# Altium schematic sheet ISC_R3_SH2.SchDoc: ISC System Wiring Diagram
size C; DrawnBy: Filiberto Clara; Engineer: Filiberto Clara; Organization: LIGO Laboratory; Address1: California Institute of Technology; Address2: Massachusetts Institute of Technology; SheetNumber: 18; SheetTotal: 39
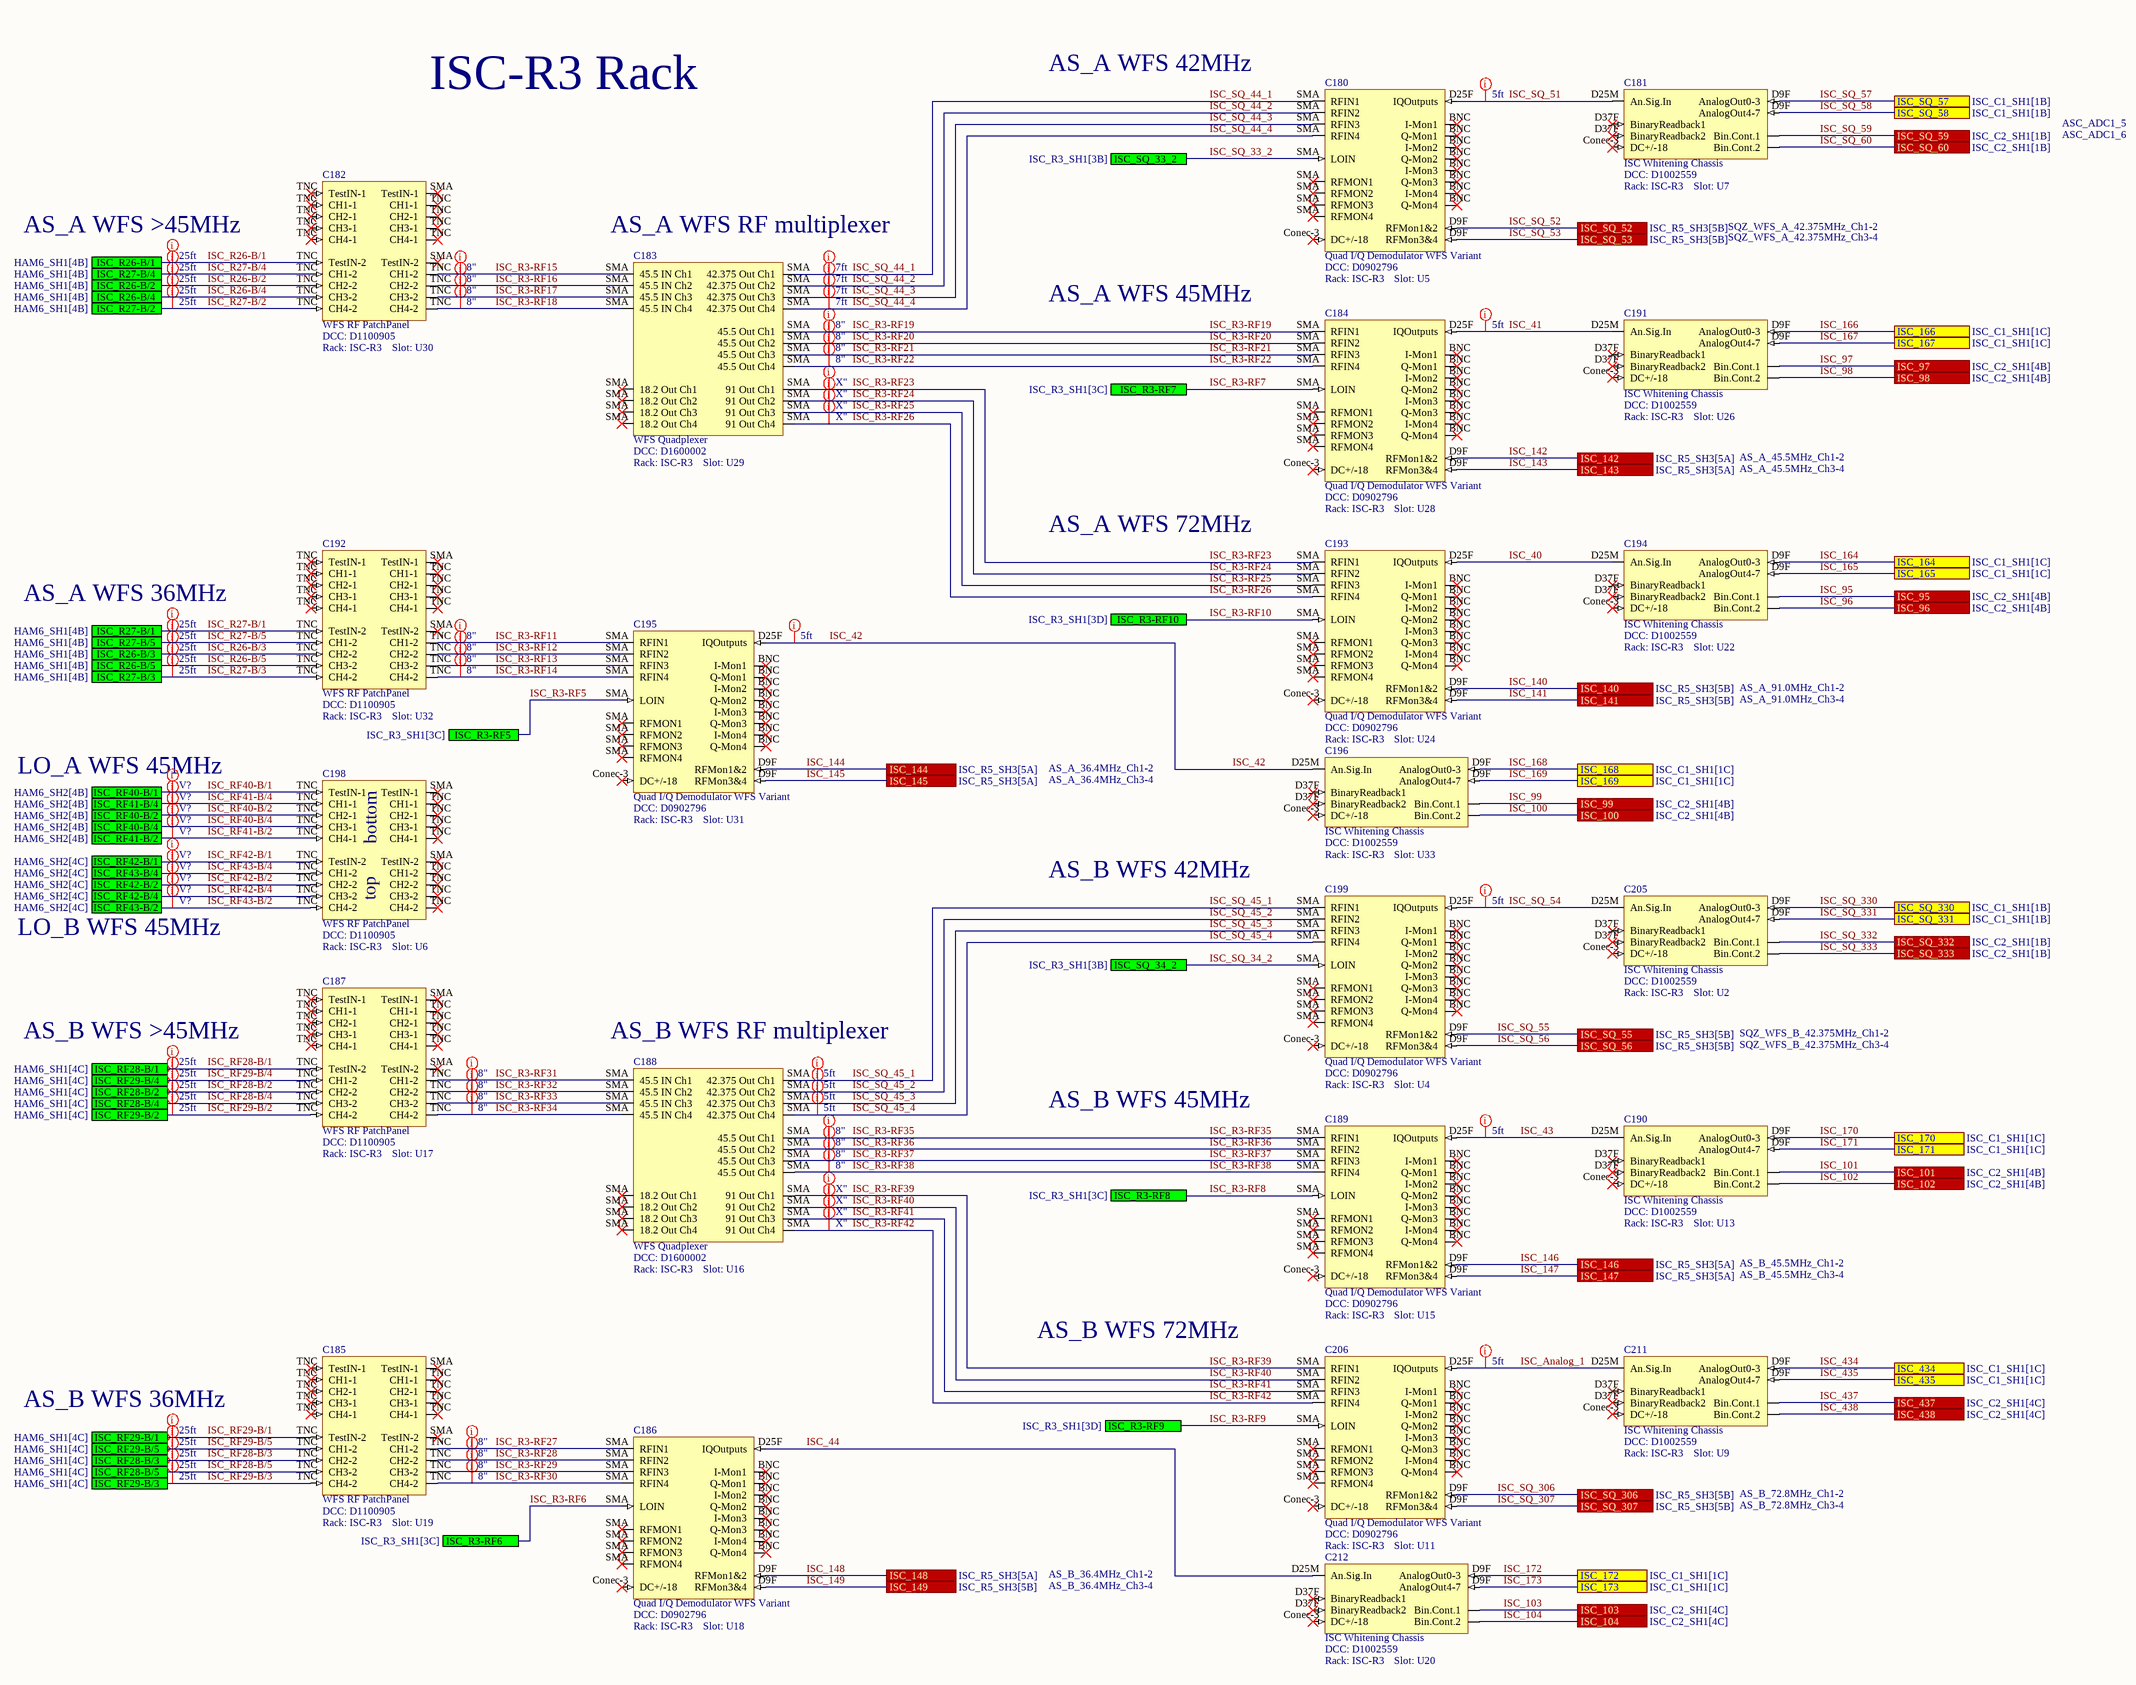
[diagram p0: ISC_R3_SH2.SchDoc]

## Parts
C180  Quad I/Q Demodulator WFS Variant  DCC: D0902796  Rack: ISC-R3  Slot: U5
C181  ISC Whitening Chassis  DCC: D1002559  Rack: ISC-R3  Slot: U7
C182  WFS RF PatchPanel  DCC: D1100905  Rack: ISC-R3  Slot: U30
C183  WFS Quadplexer  DCC: D1600002  Rack: ISC-R3  Slot: U29
C184  Quad I/Q Demodulator WFS Variant  DCC: D0902796  Rack: ISC-R3  Slot: U28
C185  WFS RF PatchPanel  DCC: D1100905  Rack: ISC-R3  Slot: U19
C186  Quad I/Q Demodulator WFS Variant  DCC: D0902796  Rack: ISC-R3  Slot: U18
C187  WFS RF PatchPanel  DCC: D1100905  Rack: ISC-R3  Slot: U17
C188  WFS Quadplexer  DCC: D1600002  Rack: ISC-R3  Slot: U16
C189  Quad I/Q Demodulator WFS Variant  DCC: D0902796  Rack: ISC-R3  Slot: U15
C190  ISC Whitening Chassis  DCC: D1002559  Rack: ISC-R3  Slot: U13
C191  ISC Whitening Chassis  DCC: D1002559  Rack: ISC-R3  Slot: U26
C192  WFS RF PatchPanel  DCC: D1100905  Rack: ISC-R3  Slot: U32
C193  Quad I/Q Demodulator WFS Variant  DCC: D0902796  Rack: ISC-R3  Slot: U24
C194  ISC Whitening Chassis  DCC: D1002559  Rack: ISC-R3  Slot: U22
C195  Quad I/Q Demodulator WFS Variant  DCC: D0902796  Rack: ISC-R3  Slot: U31
C196  ISC Whitening Chassis  DCC: D1002559  Rack: ISC-R3  Slot: U33
C198  WFS RF PatchPanel  DCC: D1100905  Rack: ISC-R3  Slot: U6
C199  Quad I/Q Demodulator WFS Variant  DCC: D0902796  Rack: ISC-R3  Slot: U4
C205  ISC Whitening Chassis  DCC: D1002559  Rack: ISC-R3  Slot: U2
C206  Quad I/Q Demodulator WFS Variant  DCC: D0902796  Rack: ISC-R3  Slot: U11
C211  ISC Whitening Chassis  DCC: D1002559  Rack: ISC-R3  Slot: U9
C212  ISC Whitening Chassis  DCC: D1002559  Rack: ISC-R3  Slot: U20

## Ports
ISC_95 (see ISC_C2_SH1[4B]), ISC_96 (see ISC_C2_SH1[4B]), ISC_97 (see ISC_C2_SH1[4B]), ISC_98 (see ISC_C2_SH1[4B]), ISC_99 (see ISC_C2_SH1[4B]), ISC_100 (see ISC_C2_SH1[4B]), ISC_101 (see ISC_C2_SH1[4B]), ISC_102 (see ISC_C2_SH1[4B]), ISC_103 (see ISC_C2_SH1[4C]), ISC_104 (see ISC_C2_SH1[4C]), ISC_140 (see ISC_R5_SH3[5B]), ISC_141 (see ISC_R5_SH3[5B]), ISC_142 (see ISC_R5_SH3[5A]), ISC_143 (see ISC_R5_SH3[5A]), ISC_144 (see ISC_R5_SH3[5A]), ISC_145 (see ISC_R5_SH3[5A]), ISC_146 (see ISC_R5_SH3[5A]), ISC_147 (see ISC_R5_SH3[5A]), ISC_148 (see ISC_R5_SH3[5A]), ISC_149 (see ISC_R5_SH3[5B]), ISC_164 (see ISC_C1_SH1[1C]), ISC_165 (see ISC_C1_SH1[1C]), ISC_166 (see ISC_C1_SH1[1C]), ISC_167 (see ISC_C1_SH1[1C]), ISC_168 (see ISC_C1_SH1[1C]), ISC_169 (see ISC_C1_SH1[1C]), ISC_170 (see ISC_C1_SH1[1C]), ISC_171 (see ISC_C1_SH1[1C]), ISC_172 (see ISC_C1_SH1[1C]), ISC_173 (see ISC_C1_SH1[1C]), ISC_434 (see ISC_C1_SH1[1C]), ISC_435 (see ISC_C1_SH1[1C]), ISC_437 (see ISC_C2_SH1[4C]), ISC_438 (see ISC_C2_SH1[4C]), ISC_R3-RF5 (see ISC_R3_SH1[3C]), ISC_R3-RF6 (see ISC_R3_SH1[3C]), ISC_R3-RF7 (see ISC_R3_SH1[3C]), ISC_R3-RF8 (see ISC_R3_SH1[3C]), ISC_R3-RF9 (see ISC_R3_SH1[3D]), ISC_R3-RF10 (see ISC_R3_SH1[3D]), ISC_R26-B/1 (see HAM6_SH1[4B]), ISC_R26-B/2 (see HAM6_SH1[4B]), ISC_R26-B/3 (see HAM6_SH1[4B]), ISC_R26-B/4 (see HAM6_SH1[4B]), ISC_R26-B/5 (see HAM6_SH1[4B]), ISC_R27-B/1 (see HAM6_SH1[4B]), ISC_R27-B/2 (see HAM6_SH1[4B]), ISC_R27-B/3 (see HAM6_SH1[4B]), ISC_R27-B/4 (see HAM6_SH1[4B]), ISC_R27-B/5 (see HAM6_SH1[4B]), ISC_RF28-B/1 (see HAM6_SH1[4C]), ISC_RF28-B/2 (see HAM6_SH1[4C]), ISC_RF28-B/3 (see HAM6_SH1[4C]), ISC_RF28-B/4 (see HAM6_SH1[4C]), ISC_RF28-B/5 (see HAM6_SH1[4C]), ISC_RF29-B/1 (see HAM6_SH1[4C]), ISC_RF29-B/2 (see HAM6_SH1[4C]), ISC_RF29-B/3 (see HAM6_SH1[4C]), ISC_RF29-B/4 (see HAM6_SH1[4C]), ISC_RF29-B/5 (see HAM6_SH1[4C]), ISC_RF40-B/1 (see HAM6_SH2[4B]), ISC_RF40-B/2 (see HAM6_SH2[4B]), ISC_RF40-B/4 (see HAM6_SH2[4B]), ISC_RF41-B/2 (see HAM6_SH2[4B]), ISC_RF41-B/4 (see HAM6_SH2[4B]), ISC_RF42-B/1 (see HAM6_SH2[4C]), ISC_RF42-B/2 (see HAM6_SH2[4C]), ISC_RF42-B/4 (see HAM6_SH2[4C]), ISC_RF43-B/2 (see HAM6_SH2[4C]), ISC_RF43-B/4 (see HAM6_SH2[4C]), ISC_SQ_33_2 (see ISC_R3_SH1[3B]), ISC_SQ_34_2 (see ISC_R3_SH1[3B]), ISC_SQ_52 (see ISC_R5_SH3[5B]), ISC_SQ_53 (see ISC_R5_SH3[5B]), ISC_SQ_55 (see ISC_R5_SH3[5B]), ISC_SQ_56 (see ISC_R5_SH3[5B]), ISC_SQ_57 (see ISC_C1_SH1[1B]), ISC_SQ_58 (see ISC_C1_SH1[1B]), ISC_SQ_59 (see ISC_C2_SH1[1B]), ISC_SQ_60 (see ISC_C2_SH1[1B]), ISC_SQ_306 (see ISC_R5_SH3[5B]), ISC_SQ_307 (see ISC_R5_SH3[5B]), ISC_SQ_330 (see ISC_C1_SH1[1B]), ISC_SQ_331 (see ISC_C1_SH1[1B]), ISC_SQ_332 (see ISC_C2_SH1[1B]), ISC_SQ_333 (see ISC_C2_SH1[1B])

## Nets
ISC_40: C193.D25F(IQOutputs) C194.D25M(An.Sig.In)
ISC_41: C184.D25F(IQOutputs) C191.D25M(An.Sig.In)
ISC_42: C195.D25F(IQOutputs) C196.D25M(An.Sig.In)
ISC_43: C189.D25F(IQOutputs) C190.D25M(An.Sig.In)
ISC_44: C186.D25F(IQOutputs) C212.D25M(An.Sig.In)
ISC_95: C194.D37F(BinaryReadback1) ; port ISC_95
ISC_96: C194.D37F(Bin.Cont.2) ; port ISC_96
ISC_97: C191.D37F(BinaryReadback1) ; port ISC_97
ISC_98: C191.D37F(Bin.Cont.2) ; port ISC_98
ISC_99: C196.D37F(BinaryReadback1) ; port ISC_99
ISC_100: C196.D37F(Bin.Cont.2) ; port ISC_100
ISC_101: C190.D37F(BinaryReadback1) ; port ISC_101
ISC_102: C190.D37F(Bin.Cont.2) ; port ISC_102
ISC_103: C212.D37F(BinaryReadback1) ; port ISC_103
ISC_104: C212.D37F(Bin.Cont.2) ; port ISC_104
ISC_140: C193.D9F(RFMon1&2) ; port ISC_140
ISC_141: C193.D9F(RFMon3&4) ; port ISC_141
ISC_142: C184.D9F(RFMon1&2) ; port ISC_142
ISC_143: C184.D9F(RFMon3&4) ; port ISC_143
ISC_144: C195.D9F(RFMon1&2) ; port ISC_144
ISC_145: C195.D9F(RFMon3&4) ; port ISC_145
ISC_146: C189.D9F(RFMon1&2) ; port ISC_146
ISC_147: C189.D9F(RFMon3&4) ; port ISC_147
ISC_148: C186.D9F(RFMon1&2) ; port ISC_148
ISC_149: C186.D9F(RFMon3&4) ; port ISC_149
ISC_164: C194.D9F(AnalogOut0-3) ; port ISC_164
ISC_165: C194.D9F(AnalogOut4-7) ; port ISC_165
ISC_166: C191.D9F(AnalogOut0-3) ; port ISC_166
ISC_167: C191.D9F(AnalogOut4-7) ; port ISC_167
ISC_168: C196.D9F(AnalogOut0-3) ; port ISC_168
ISC_169: C196.D9F(AnalogOut4-7) ; port ISC_169
ISC_170: C190.D9F(AnalogOut0-3) ; port ISC_170
ISC_171: C190.D9F(AnalogOut4-7) ; port ISC_171
ISC_172: C212.D9F(AnalogOut0-3) ; port ISC_172
ISC_173: C212.D9F(AnalogOut4-7) ; port ISC_173
ISC_434: C211.D9F(AnalogOut0-3) ; port ISC_434
ISC_435: C211.D9F(AnalogOut4-7) ; port ISC_435
ISC_437: C211.D37F(BinaryReadback1) ; port ISC_437
ISC_438: C211.D37F(Bin.Cont.2) ; port ISC_438
ISC_Analog_1: C206.D25F(IQOutputs) C211.D25M(An.Sig.In)
ISC_R3-RF5: C195.SMA(LOIN) ; port ISC_R3-RF5
ISC_R3-RF6: C186.SMA(LOIN) ; port ISC_R3-RF6
ISC_R3-RF7: C184.SMA(LOIN) ; port ISC_R3-RF7
ISC_R3-RF8: C189.SMA(LOIN) ; port ISC_R3-RF8
ISC_R3-RF9: C206.SMA(LOIN) ; port ISC_R3-RF9
ISC_R3-RF10: C193.SMA(LOIN) ; port ISC_R3-RF10
ISC_R3-RF11: C192.TNC(CH1-2) C195.SMA(RFIN1)
ISC_R3-RF12: C192.TNC(CH2-2) C195.SMA(RFIN2)
ISC_R3-RF13: C192.TNC(CH3-2) C195.SMA(RFIN3)
ISC_R3-RF14: C192.TNC(CH4-2) C195.SMA(RFIN4)
ISC_R3-RF15: C182.TNC(CH1-2) C183.SMA(45.5_IN_Ch1)
ISC_R3-RF16: C182.TNC(CH2-2) C183.SMA(45.5_IN_Ch2)
ISC_R3-RF17: C182.TNC(CH3-2) C183.SMA(45.5_IN_Ch3)
ISC_R3-RF18: C182.TNC(CH4-2) C183.SMA(45.5_IN_Ch4)
ISC_R3-RF19: C183.SMA(45.5_Out_Ch1) C184.SMA(RFIN1)
ISC_R3-RF20: C183.SMA(45.5_Out_Ch2) C184.SMA(RFIN2)
ISC_R3-RF21: C183.SMA(45.5_Out_Ch3) C184.SMA(RFIN3)
ISC_R3-RF22: C183.SMA(45.5_Out_Ch4) C184.SMA(RFIN4)
ISC_R3-RF23: C183.SMA(91_Out_Ch1) C193.SMA(RFIN1)
ISC_R3-RF24: C183.SMA(91_Out_Ch2) C193.SMA(RFIN2)
ISC_R3-RF25: C183.SMA(91_Out_Ch3) C193.SMA(RFIN3)
ISC_R3-RF26: C183.SMA(91_Out_Ch4) C193.SMA(RFIN4)
ISC_R3-RF27: C185.TNC(CH1-2) C186.SMA(RFIN1)
ISC_R3-RF28: C185.TNC(CH2-2) C186.SMA(RFIN2)
ISC_R3-RF29: C185.TNC(CH3-2) C186.SMA(RFIN3)
ISC_R3-RF30: C185.TNC(CH4-2) C186.SMA(RFIN4)
ISC_R3-RF31: C187.TNC(CH1-2) C188.SMA(45.5_IN_Ch1)
ISC_R3-RF32: C187.TNC(CH2-2) C188.SMA(45.5_IN_Ch2)
ISC_R3-RF33: C187.TNC(CH3-2) C188.SMA(45.5_IN_Ch3)
ISC_R3-RF34: C187.TNC(CH4-2) C188.SMA(45.5_IN_Ch4)
ISC_R3-RF35: C188.SMA(45.5_Out_Ch1) C189.SMA(RFIN1)
ISC_R3-RF36: C188.SMA(45.5_Out_Ch2) C189.SMA(RFIN2)
ISC_R3-RF37: C188.SMA(45.5_Out_Ch3) C189.SMA(RFIN3)
ISC_R3-RF38: C188.SMA(45.5_Out_Ch4) C189.SMA(RFIN4)
ISC_R3-RF39: C188.SMA(91_Out_Ch1) C206.SMA(RFIN1)
ISC_R3-RF40: C188.SMA(91_Out_Ch2) C206.SMA(RFIN2)
ISC_R3-RF41: C188.SMA(91_Out_Ch3) C206.SMA(RFIN3)
ISC_R3-RF42: C188.SMA(91_Out_Ch4) C206.SMA(RFIN4)
ISC_R26-B/1: C182.TNC(TestIN-1) ; port ISC_R26-B/1
ISC_R26-B/2: C182.TNC(CH2-2) ; port ISC_R26-B/2
ISC_R26-B/3: C192.TNC(CH2-2) ; port ISC_R26-B/3
ISC_R26-B/4: C182.TNC(CH3-2) ; port ISC_R26-B/4
ISC_R26-B/5: C192.TNC(CH3-2) ; port ISC_R26-B/5
ISC_R27-B/1: C192.TNC(TestIN-1) ; port ISC_R27-B/1
ISC_R27-B/2: C182.TNC(CH4-2) ; port ISC_R27-B/2
ISC_R27-B/3: C192.TNC(CH4-2) ; port ISC_R27-B/3
ISC_R27-B/4: C182.TNC(CH1-2) ; port ISC_R27-B/4
ISC_R27-B/5: C192.TNC(CH1-2) ; port ISC_R27-B/5
ISC_RF28-B/1: C187.TNC(TestIN-1) ; port ISC_RF28-B/1
ISC_RF28-B/2: C187.TNC(CH2-2) ; port ISC_RF28-B/2
ISC_RF28-B/3: C185.TNC(CH2-2) ; port ISC_RF28-B/3
ISC_RF28-B/4: C187.TNC(CH3-2) ; port ISC_RF28-B/4
ISC_RF28-B/5: C185.TNC(CH3-2) ; port ISC_RF28-B/5
ISC_RF29-B/1: C185.TNC(TestIN-1) ; port ISC_RF29-B/1
ISC_RF29-B/2: C187.TNC(CH4-2) ; port ISC_RF29-B/2
ISC_RF29-B/3: C185.TNC(CH4-2) ; port ISC_RF29-B/3
ISC_RF29-B/4: C187.TNC(CH1-2) ; port ISC_RF29-B/4
ISC_RF29-B/5: C185.TNC(CH1-2) ; port ISC_RF29-B/5
ISC_RF40-B/1: C198.TNC(TestIN-1) ; port ISC_RF40-B/1
ISC_RF40-B/2: C198.TNC(CH2-1) ; port ISC_RF40-B/2
ISC_RF40-B/4: C198.TNC(CH3-1) ; port ISC_RF40-B/4
ISC_RF41-B/2: C198.TNC(CH4-1) ; port ISC_RF41-B/2
ISC_RF41-B/4: C198.TNC(CH1-1) ; port ISC_RF41-B/4
ISC_RF42-B/1: C198.TNC(TestIN-2) ; port ISC_RF42-B/1
ISC_RF42-B/2: C198.TNC(CH2-2) ; port ISC_RF42-B/2
ISC_RF42-B/4: C198.TNC(CH3-2) ; port ISC_RF42-B/4
ISC_RF43-B/2: C198.TNC(CH4-2) ; port ISC_RF43-B/2
ISC_RF43-B/4: C198.TNC(CH1-2) ; port ISC_RF43-B/4
ISC_SQ_33_2: C180.SMA(LOIN) ; port ISC_SQ_33_2
ISC_SQ_34_2: C199.SMA(LOIN) ; port ISC_SQ_34_2
ISC_SQ_44_1: C180.SMA(RFIN1) C183.SMA(42.375_Out_Ch1)
ISC_SQ_44_2: C180.SMA(RFIN2) C183.SMA(42.375_Out_Ch2)
ISC_SQ_44_3: C180.SMA(RFIN3) C183.SMA(42.375_Out_Ch3)
ISC_SQ_44_4: C180.SMA(RFIN4) C183.SMA(42.375_Out_Ch4)
ISC_SQ_45_1: C188.SMA(42.375_Out_Ch1) C199.SMA(RFIN1)
ISC_SQ_45_2: C188.SMA(42.375_Out_Ch2) C199.SMA(RFIN2)
ISC_SQ_45_3: C188.SMA(42.375_Out_Ch3) C199.SMA(RFIN3)
ISC_SQ_45_4: C188.SMA(42.375_Out_Ch4) C199.SMA(RFIN4)
ISC_SQ_51: C180.D25F(IQOutputs) C181.D25M(An.Sig.In)
ISC_SQ_52: C180.D9F(RFMon1&2) ; port ISC_SQ_52
ISC_SQ_53: C180.D9F(RFMon3&4) ; port ISC_SQ_53
ISC_SQ_54: C199.D25F(IQOutputs) C205.D25M(An.Sig.In)
ISC_SQ_55: C199.D9F(RFMon1&2) ; port ISC_SQ_55
ISC_SQ_56: C199.D9F(RFMon3&4) ; port ISC_SQ_56
ISC_SQ_57: C181.D9F(AnalogOut0-3) ; port ISC_SQ_57
ISC_SQ_58: C181.D9F(AnalogOut4-7) ; port ISC_SQ_58
ISC_SQ_59: C181.D37F(BinaryReadback1) ; port ISC_SQ_59
ISC_SQ_60: C181.D37F(Bin.Cont.2) ; port ISC_SQ_60
ISC_SQ_306: C206.D9F(RFMon1&2) ; port ISC_SQ_306
ISC_SQ_307: C206.D9F(RFMon3&4) ; port ISC_SQ_307
ISC_SQ_330: C205.D9F(AnalogOut0-3) ; port ISC_SQ_330
ISC_SQ_331: C205.D9F(AnalogOut4-7) ; port ISC_SQ_331
ISC_SQ_332: C205.D37F(BinaryReadback1) ; port ISC_SQ_332
ISC_SQ_333: C205.D37F(Bin.Cont.2) ; port ISC_SQ_333

Not connected (* = marked no-connect by the designer): C180 BNC(I-Mon1)* Conec-3(DC+/-18)*; C181 Conec-3(DC+/-18)*; C182 SMA(TestIN-1)*; C184 BNC(I-Mon1)* Conec-3(DC+/-18)*; C185 SMA(TestIN-1)*; C186 BNC(I-Mon1)* Conec-3(DC+/-18)*; C187 SMA(TestIN-1)*; C189 BNC(I-Mon1)* Conec-3(DC+/-18)*; C190 Conec-3(DC+/-18)*; C191 Conec-3(DC+/-18)*; C192 SMA(TestIN-1)*; C193 BNC(I-Mon1)* Conec-3(DC+/-18)*; C194 Conec-3(DC+/-18)*; C195 BNC(I-Mon1)* Conec-3(DC+/-18)*; C196 Conec-3(DC+/-18)*; C198 SMA(TestIN-1)*; C199 BNC(I-Mon1)* Conec-3(DC+/-18)*; C205 Conec-3(DC+/-18)*; C206 BNC(I-Mon1)* Conec-3(DC+/-18)*; C211 Conec-3(DC+/-18)*; C212 Conec-3(DC+/-18)*

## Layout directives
Length: 5ft: ISC_41, ISC_42, ISC_43, ISC_Analog_1, ISC_SQ_45_1, ISC_SQ_45_2, ISC_SQ_45_3, ISC_SQ_45_4, ISC_SQ_51, ISC_SQ_54
Length: 8": ISC_R3-RF11, ISC_R3-RF12, ISC_R3-RF13, ISC_R3-RF14, ISC_R3-RF15, ISC_R3-RF16, ISC_R3-RF17, ISC_R3-RF18, ISC_R3-RF19, ISC_R3-RF20, ISC_R3-RF21, ISC_R3-RF22, ISC_R3-RF27, ISC_R3-RF28, ISC_R3-RF29, ISC_R3-RF30, ISC_R3-RF31, ISC_R3-RF32, ISC_R3-RF33, ISC_R3-RF34, ISC_R3-RF35, ISC_R3-RF36, ISC_R3-RF37, ISC_R3-RF38
Length: 25ft: ISC_R26-B/1, ISC_R26-B/2, ISC_R26-B/3, ISC_R26-B/4, ISC_R26-B/5, ISC_R27-B/1, ISC_R27-B/2, ISC_R27-B/3, ISC_R27-B/4, ISC_R27-B/5, ISC_RF28-B/1, ISC_RF28-B/2, ISC_RF28-B/3, ISC_RF28-B/4, ISC_RF28-B/5, ISC_RF29-B/1, ISC_RF29-B/2, ISC_RF29-B/3, ISC_RF29-B/4, ISC_RF29-B/5
Length: X": ISC_R3-RF23, ISC_R3-RF24, ISC_R3-RF25, ISC_R3-RF26, ISC_R3-RF39, ISC_R3-RF40, ISC_R3-RF41, ISC_R3-RF42
Length: 7ft: ISC_SQ_44_1, ISC_SQ_44_2, ISC_SQ_44_3, ISC_SQ_44_4
Length: V?: ISC_RF40-B/1, ISC_RF40-B/2, ISC_RF40-B/4, ISC_RF41-B/2, ISC_RF41-B/4, ISC_RF42-B/1, ISC_RF42-B/2, ISC_RF42-B/4, ISC_RF43-B/2, ISC_RF43-B/4

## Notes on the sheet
- ISC-R3 Rack
- AS_A WFS 42MHz
- ASC_ADC1_5
- ASC_ADC1_6
- AS_A WFS >45MHz
- (near C183) AS_A WFS RF multiplexer
- SQZ_WFS_A_42.375MHz_Ch1-2
- SQZ_WFS_A_42.375MHz_Ch3-4
- AS_A WFS 45MHz
- AS_A_45.5MHz_Ch1-2
- AS_A_45.5MHz_Ch3-4
- AS_A WFS 72MHz
- AS_A WFS 36MHz
- AS_A_91.0MHz_Ch1-2
- AS_A_91.0MHz_Ch3-4
- LO_A WFS 45MHz
- AS_A_36.4MHz_Ch1-2
- AS_A_36.4MHz_Ch3-4
- (near C198) bottom
- AS_B WFS 42MHz
- LO_B WFS 45MHz
- (near C198) top
- AS_B WFS >45MHz
- (near C188) AS_B WFS RF multiplexer
- SQZ_WFS_B_42.375MHz_Ch1-2
- SQZ_WFS_B_42.375MHz_Ch3-4
- AS_B WFS 45MHz
- AS_B_45.5MHz_Ch1-2
- AS_B_45.5MHz_Ch3-4
- AS_B WFS 72MHz
- AS_B WFS 36MHz
- AS_B_72.8MHz_Ch1-2
- AS_B_72.8MHz_Ch3-4
- AS_B_36.4MHz_Ch1-2
- AS_B_36.4MHz_Ch3-4

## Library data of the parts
C180 C184 C186 C189 C193 C195 C199 C206 = QuadIQdemod_WFS: Serial: Sxxxxxxx; System: ISC
C181 C190 C191 C194 C196 C205 C211 C212 = ISC Whitening: Serial: Sxxxxxxx
C182 C185 C187 C192 C198 = WFS RFPD PatchPanel: Serial: Sxxxxxxx; System: ISC
C183 C188 = WFS Quadplexer: Serial: Sxxxxxxx; System: ISC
